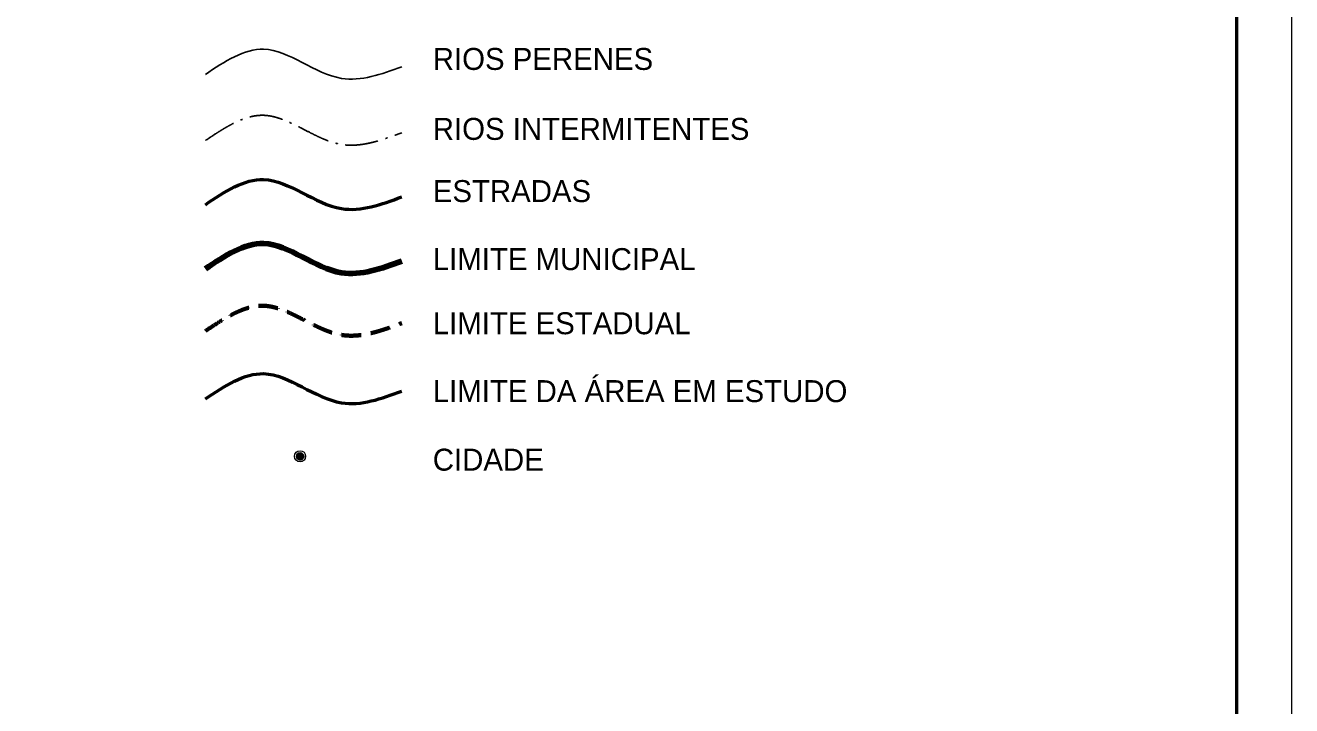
# Model space of a CAD drawing. Extents: x 512883 to 1063249, y 8784064 to 9081064.
# Drawn here: x 947963 to 1063249, y 8846031 to 8907998 of the extents above; entities that cross this region are included whole.
import ezdxf

# ---------------------------------------------------------------- set-up
doc = ezdxf.new("R2010")
doc.units = 0
doc.header["$LTSCALE"] = 600
doc.linetypes.add('DOT_DASHED', pattern=[7.7, 5, -1.2, 0.3, -1.2])
doc.linetypes.add('MEDIUM_DASHED', pattern=[4.5, 3, -1.5])
for name, color, linetype, lineweight in [('1', 7, 'Continuous', 25), ('10', 7, 'Continuous', 53), ('13', 7, 'Continuous', 90), ('3', 7, 'Continuous', 25)]:
    doc.layers.add(name, color=color, linetype=linetype, lineweight=lineweight)

msp = doc.modelspace()

# ---------------------------------------------------------------- linework, layer by layer
at = {"layer": '1', "lineweight": 13}
for points in [[(512883.1, 8784063.9), (1063248.6, 8784063.9), (1063248.6, 9081063.9), (512883.1, 9081063.9)], [(537883.1, 9076063.9), (1058248.6, 9076063.9), (1058248.6, 8789063.9), (537883.1, 8789063.9)]]:
    msp.add_lwpolyline(points, close=True, dxfattribs=at)
at = {"layer": '1', "lineweight": 53}
msp.add_lwpolyline([(537883.1, 8789063.9), (1058248.6, 8789063.9), (1058248.6, 9076063.9), (537883.1, 9076063.9)], close=True, dxfattribs=at)
at = {"layer": '10', "lineweight": 13}
for p, q in [((972725.2, 8868967.2), (973225.6, 8868967.2)), ((972754.3, 8868997.2), (973195.9, 8868997.2)), ((972793.9, 8869027.2), (973156.3, 8869027.2)), ((972851.2, 8869057.2), (973099, 8869057.2)), ((972642.7, 8868757.2), (973307.5, 8868757.2)), ((972643.3, 8868727.2), (973307.2, 8868727.2)), ((972644.8, 8868787.2), (973305.4, 8868787.2)), ((972646.3, 8868697.2), (973303.9, 8868697.2)), ((972649.6, 8868817.2), (973300.6, 8868817.2)), ((972652.3, 8868667.2), (973297.9, 8868667.2)), ((972657.7, 8868847.2), (973292.5, 8868847.2)), ((972661.3, 8868637.2), (973288.9, 8868637.2)), ((972668.5, 8868877.2), (973281.7, 8868877.5)), ((972673.9, 8868607.2), (973276.6, 8868607.5)), ((972682.9, 8868907.2), (973267.6, 8868907.2)), ((972689.8, 8868577.2), (973260.4, 8868577.2)), ((972701.2, 8868937.2), (973249.3, 8868937.2)), ((972710.5, 8868547.2), (973240, 8868547.5)), ((972735.7, 8868516.9), (973214.8, 8868517.2)), ((972769, 8868487.2), (973181.2, 8868487.2)), ((972814, 8868457.2), (973136.2, 8868457.2)), ((972887.8, 8868427.2), (973062.1, 8868427.2))]:
    msp.add_line(p, q, dxfattribs=at)
at = {"layer": '10', "lineweight": 25}
msp.add_lwpolyline([(537883.1, 9076063.9), (1058248.6, 9076063.9), (1058248.6, 8789063.9), (537883.1, 8789063.9)], close=True, dxfattribs=at)
at = {"layer": '10', "lineweight": 13}
for radius in [506.1, 332.9]:
    msp.add_circle((972975.2, 8868748.2), radius, dxfattribs=at)
at = {"layer": '10', "lineweight": 25}
msp.add_spline([(964351.2, 8903519.8), (969660, 8905821.1), (976738.5, 8903165.8), (982224.3, 8904227.9)], degree=3, dxfattribs=at)
at = {"layer": '10', "linetype": 'DOT_DASHED', "lineweight": 25}
msp.add_spline([(964351.2, 8897501.2), (969660, 8899802.4), (976738.5, 8897147.2), (982224.3, 8898209.3)], degree=3, dxfattribs=at)
at = {"layer": '10'}
for points in [[(964351.2, 8891659.6), (969660, 8893960.8), (976738.5, 8891305.5), (982224.3, 8892367.6)], [(964351.2, 8873971.5), (969660, 8876272.7), (976738.5, 8873617.4), (982224.3, 8874679.5)]]:
    msp.add_spline(points, degree=3, dxfattribs=at)
at = {"layer": '10', "lineweight": 90}
msp.add_spline([(964351.2, 8885817.9), (969660, 8888119.2), (976738.5, 8885463.9), (982224.3, 8886526)], degree=3, dxfattribs=at)
at = {"layer": '13', "linetype": 'MEDIUM_DASHED', "lineweight": 70}
msp.add_spline([(964351.2, 8880153.3), (969660, 8882454.6), (976738.5, 8879799.3), (982224.3, 8880861.4)], degree=3, dxfattribs=at)
at = {"layer": '3'}
msp.add_lwpolyline([(537883.1, 9076063.9), (1058248.6, 9076063.9), (1058248.6, 8789063.9), (537883.1, 8789063.9)], close=True, dxfattribs=at)

# ---------------------------------------------------------------- texts
at = {"layer": '10'}
for s, p in [('RIOS PERENES', (985055.7, 8903936)), ('RIOS INTERMITENTES', (985055.7, 8897563.3)), ('ESTRADAS', (985055.7, 8891898.7)), ('LIMITE MUNICIPAL', (985055.7, 8885703)), ('LIMITE ESTADUAL', (985055.7, 8879861.4)), ('LIMITE DA ÁREA EM ESTUDO', (985055.7, 8873679.5)), ('CIDADE', (985055.7, 8867438.1))]:
    msp.add_text(s, height=2000, dxfattribs=at).set_placement(p)

doc.saveas('drawing.dxf')
